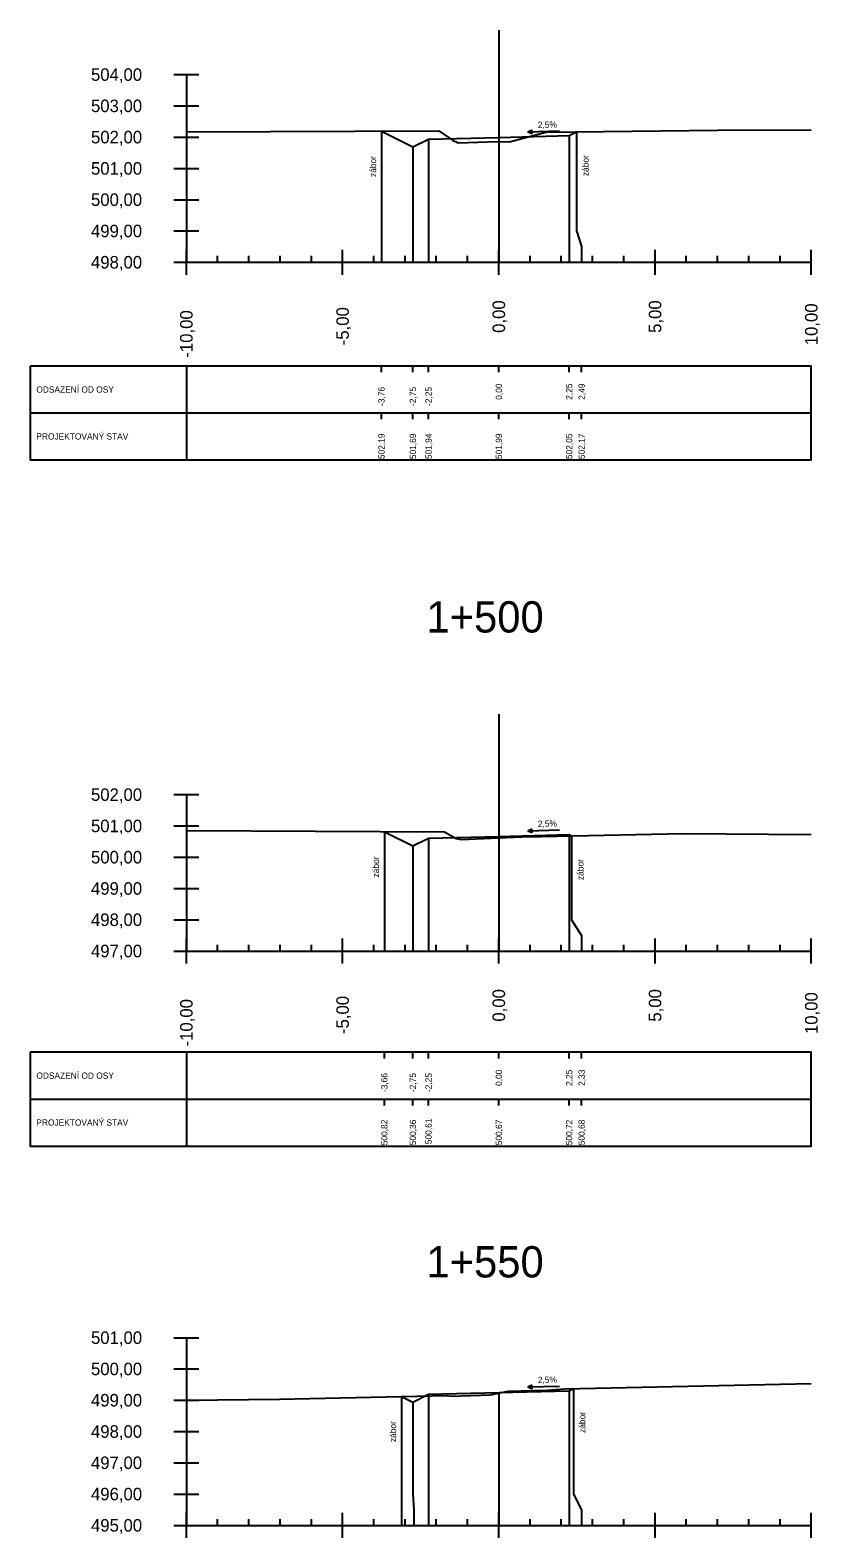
# Model space of a CAD drawing. Extents: x -631407 to -631215, y -1089700 to -1088598.
# Drawn here: x -631314.72 to -631289.44, y -1088856.74 to -1088808.54 of the extents above; entities that cross this region are included whole.
import ezdxf

# ---------------------------------------------------------------- set-up
doc = ezdxf.new("R2010")
doc.units = 0
for name, color, linetype in [('59', 7, 'Continuous'), ('NIVELETA_VYSKY', 7, 'Continuous'), ('REZ_BODY', 7, 'Continuous'), ('REZ_ODSTUPY', 7, 'Continuous'), ('REZ_POPIS', 7, 'Continuous'), ('REZ_RAMY', 7, 'Continuous'), ('REZ_STANICENI', 7, 'Continuous'), ('REZ_SVISLE', 7, 'Continuous'), ('REZ_TENKA', 7, 'Continuous'), ('REZ_TLUSTA', 7, 'Continuous'), ('TABULKA_POPIS', 7, 'Continuous'), ('TEREN', 7, 'Continuous'), ('zábor', 7, 'Continuous')]:
    doc.layers.add(name, color=color, linetype=linetype)

msp = doc.modelspace()

# ---------------------------------------------------------------- linework, layer by layer
at = {"layer": '59'}
for p, q in [((-631310.116, -1088809.959), (-631309.316, -1088809.959)), ((-631309.716, -1088809.959), (-631309.716, -1088815.959)), ((-631310.116, -1088810.959), (-631309.316, -1088810.959)), ((-631310.116, -1088811.959), (-631309.316, -1088811.959)), ((-631310.116, -1088812.959), (-631309.316, -1088812.959)), ((-631310.116, -1088813.959), (-631309.316, -1088813.959)), ((-631310.116, -1088814.959), (-631309.316, -1088814.959)), ((-631310.116, -1088815.959), (-631309.316, -1088815.959)), ((-631310.116, -1088832.981), (-631309.316, -1088832.981)), ((-631309.716, -1088832.981), (-631309.716, -1088837.981)), ((-631310.116, -1088833.981), (-631309.316, -1088833.981)), ((-631310.116, -1088834.981), (-631309.316, -1088834.981)), ((-631310.116, -1088835.981), (-631309.316, -1088835.981)), ((-631310.116, -1088836.981), (-631309.316, -1088836.981)), ((-631310.116, -1088837.981), (-631309.316, -1088837.981)), ((-631310.116, -1088850.343), (-631309.316, -1088850.343)), ((-631309.716, -1088850.343), (-631309.716, -1088856.343)), ((-631310.116, -1088851.343), (-631309.316, -1088851.343)), ((-631310.116, -1088852.343), (-631309.316, -1088852.343)), ((-631310.116, -1088853.343), (-631309.316, -1088853.343)), ((-631310.116, -1088854.343), (-631309.316, -1088854.343)), ((-631310.116, -1088855.343), (-631309.316, -1088855.343)), ((-631310.116, -1088856.343), (-631309.316, -1088856.343))]:
    msp.add_line(p, q, dxfattribs=at)
at = {"layer": 'REZ_RAMY'}
for p, q in [((-631314.716, -1088819.278), (-631314.716, -1088822.278)), ((-631309.716, -1088819.278), (-631309.716, -1088822.278)), ((-631303.472, -1088819.478), (-631303.472, -1088819.278)), ((-631302.466, -1088819.478), (-631302.466, -1088819.278)), ((-631301.966, -1088819.478), (-631301.966, -1088819.278)), ((-631299.716, -1088819.478), (-631299.716, -1088819.278)), ((-631297.466, -1088819.478), (-631297.466, -1088819.278)), ((-631297.066, -1088819.478), (-631297.066, -1088819.278)), ((-631314.716, -1088820.778), (-631289.716, -1088820.778)), ((-631303.472, -1088820.978), (-631303.472, -1088820.778)), ((-631302.466, -1088820.978), (-631302.466, -1088820.778)), ((-631301.966, -1088820.978), (-631301.966, -1088820.778)), ((-631299.716, -1088820.978), (-631299.716, -1088820.778)), ((-631297.466, -1088820.978), (-631297.466, -1088820.778)), ((-631297.066, -1088820.978), (-631297.066, -1088820.778)), ((-631314.716, -1088841.215), (-631314.716, -1088844.215)), ((-631309.716, -1088841.215), (-631309.716, -1088844.215)), ((-631303.38, -1088841.415), (-631303.38, -1088841.215)), ((-631302.466, -1088841.415), (-631302.466, -1088841.215)), ((-631301.966, -1088841.415), (-631301.966, -1088841.215)), ((-631299.716, -1088841.415), (-631299.716, -1088841.215)), ((-631297.466, -1088841.415), (-631297.466, -1088841.215)), ((-631297.066, -1088841.415), (-631297.066, -1088841.215)), ((-631314.716, -1088842.715), (-631289.716, -1088842.715)), ((-631303.38, -1088842.915), (-631303.38, -1088842.715)), ((-631302.466, -1088842.915), (-631302.466, -1088842.715)), ((-631301.966, -1088842.915), (-631301.966, -1088842.715)), ((-631299.716, -1088842.915), (-631299.716, -1088842.715)), ((-631297.466, -1088842.915), (-631297.466, -1088842.715)), ((-631297.066, -1088842.915), (-631297.066, -1088842.715))]:
    msp.add_line(p, q, dxfattribs=at)
for points in [[(-631314.716, -1088819.278), (-631314.716, -1088822.278), (-631289.716, -1088822.278), (-631289.716, -1088819.278)], [(-631314.716, -1088841.215), (-631314.716, -1088844.215), (-631289.716, -1088844.215), (-631289.716, -1088841.215)]]:
    msp.add_lwpolyline(points, close=True, dxfattribs=at)
at = {"layer": 'REZ_SVISLE'}
for points in [[(-631303.472, -1088811.77), (-631303.472, -1088814.959), (-631303.472, -1088815.459), (-631303.472, -1088815.959)], [(-631297.466, -1088811.911), (-631297.466, -1088814.959), (-631297.466, -1088815.459), (-631297.466, -1088815.959)], [(-631297.226, -1088811.791), (-631297.226, -1088814.959), (-631297.066, -1088815.459), (-631297.066, -1088815.959)], [(-631302.466, -1088812.274), (-631302.466, -1088814.959), (-631302.466, -1088815.459), (-631302.466, -1088815.959)], [(-631301.966, -1088812.024), (-631301.966, -1088814.959), (-631301.966, -1088815.459), (-631301.966, -1088815.959)], [(-631299.716, -1088811.967), (-631299.716, -1088814.959), (-631299.716, -1088815.459), (-631299.716, -1088815.959)], [(-631303.38, -1088834.165), (-631303.38, -1088836.981), (-631303.38, -1088837.481), (-631303.38, -1088837.981)], [(-631301.966, -1088834.372), (-631301.966, -1088836.981), (-631301.966, -1088837.481), (-631301.966, -1088837.981)], [(-631299.716, -1088834.316), (-631299.716, -1088836.981), (-631299.716, -1088837.481), (-631299.716, -1088837.981)], [(-631297.466, -1088834.259), (-631297.466, -1088836.981), (-631297.466, -1088837.481), (-631297.466, -1088837.981)], [(-631297.389, -1088834.298), (-631297.389, -1088836.981), (-631297.066, -1088837.481), (-631297.066, -1088837.981)], [(-631302.466, -1088834.622), (-631302.466, -1088836.981), (-631302.466, -1088837.481), (-631302.466, -1088837.981)], [(-631302.833, -1088852.22), (-631302.833, -1088855.343), (-631302.833, -1088855.843), (-631302.833, -1088856.343)], [(-631302.466, -1088852.403), (-631302.466, -1088855.343), (-631302.433, -1088855.843), (-631302.433, -1088856.343)], [(-631301.966, -1088852.153), (-631301.966, -1088855.343), (-631301.966, -1088855.843), (-631301.966, -1088856.343)], [(-631299.716, -1088852.097), (-631299.716, -1088855.343), (-631299.716, -1088855.843), (-631299.716, -1088856.343)], [(-631297.466, -1088852.041), (-631297.466, -1088855.343), (-631297.466, -1088855.843), (-631297.466, -1088856.343)], [(-631297.331, -1088851.973), (-631297.331, -1088855.343), (-631297.066, -1088855.843), (-631297.066, -1088856.343)]]:
    msp.add_lwpolyline(points, dxfattribs=at)
at = {"layer": 'REZ_TENKA'}
for p, q in [((-631308.716, -1088815.959), (-631308.716, -1088815.759)), ((-631307.716, -1088815.959), (-631307.716, -1088815.759)), ((-631306.716, -1088815.959), (-631306.716, -1088815.759)), ((-631305.716, -1088815.959), (-631305.716, -1088815.759)), ((-631303.716, -1088815.959), (-631303.716, -1088815.759)), ((-631302.716, -1088815.959), (-631302.716, -1088815.759)), ((-631301.716, -1088815.959), (-631301.716, -1088815.759)), ((-631300.716, -1088815.959), (-631300.716, -1088815.759)), ((-631298.716, -1088815.959), (-631298.716, -1088815.759)), ((-631297.716, -1088815.959), (-631297.716, -1088815.759)), ((-631296.716, -1088815.959), (-631296.716, -1088815.759)), ((-631295.716, -1088815.959), (-631295.716, -1088815.759)), ((-631293.716, -1088815.959), (-631293.716, -1088815.759)), ((-631292.716, -1088815.959), (-631292.716, -1088815.759)), ((-631291.716, -1088815.959), (-631291.716, -1088815.759)), ((-631290.716, -1088815.959), (-631290.716, -1088815.759)), ((-631308.716, -1088837.981), (-631308.716, -1088837.781)), ((-631307.716, -1088837.981), (-631307.716, -1088837.781)), ((-631306.716, -1088837.981), (-631306.716, -1088837.781)), ((-631305.716, -1088837.981), (-631305.716, -1088837.781)), ((-631303.716, -1088837.981), (-631303.716, -1088837.781)), ((-631302.716, -1088837.981), (-631302.716, -1088837.781)), ((-631301.716, -1088837.981), (-631301.716, -1088837.781)), ((-631300.716, -1088837.981), (-631300.716, -1088837.781)), ((-631298.716, -1088837.981), (-631298.716, -1088837.781)), ((-631297.716, -1088837.981), (-631297.716, -1088837.781)), ((-631296.716, -1088837.981), (-631296.716, -1088837.781)), ((-631295.716, -1088837.981), (-631295.716, -1088837.781)), ((-631293.716, -1088837.981), (-631293.716, -1088837.781)), ((-631292.716, -1088837.981), (-631292.716, -1088837.781)), ((-631291.716, -1088837.981), (-631291.716, -1088837.781)), ((-631290.716, -1088837.981), (-631290.716, -1088837.781)), ((-631308.716, -1088856.343), (-631308.716, -1088856.143)), ((-631307.716, -1088856.343), (-631307.716, -1088856.143)), ((-631306.716, -1088856.343), (-631306.716, -1088856.143)), ((-631305.716, -1088856.343), (-631305.716, -1088856.143)), ((-631303.716, -1088856.343), (-631303.716, -1088856.143)), ((-631302.716, -1088856.343), (-631302.716, -1088856.143)), ((-631301.716, -1088856.343), (-631301.716, -1088856.143)), ((-631300.716, -1088856.343), (-631300.716, -1088856.143)), ((-631298.716, -1088856.343), (-631298.716, -1088856.143)), ((-631297.716, -1088856.343), (-631297.716, -1088856.143)), ((-631296.716, -1088856.343), (-631296.716, -1088856.143)), ((-631295.716, -1088856.343), (-631295.716, -1088856.143)), ((-631293.716, -1088856.343), (-631293.716, -1088856.143)), ((-631292.716, -1088856.343), (-631292.716, -1088856.143)), ((-631291.716, -1088856.343), (-631291.716, -1088856.143)), ((-631290.716, -1088856.343), (-631290.716, -1088856.143))]:
    msp.add_line(p, q, dxfattribs=at)
at = {"layer": 'REZ_TLUSTA'}
for p, q in [((-631299.716, -1088808.539), (-631299.716, -1088815.959)), ((-631309.716, -1088816.359), (-631309.716, -1088815.559)), ((-631304.716, -1088816.359), (-631304.716, -1088815.559)), ((-631299.716, -1088816.359), (-631299.716, -1088815.559)), ((-631294.716, -1088816.359), (-631294.716, -1088815.559)), ((-631289.716, -1088816.359), (-631289.716, -1088815.559)), ((-631309.716, -1088815.959), (-631289.716, -1088815.959)), ((-631299.716, -1088830.408), (-631299.716, -1088837.981)), ((-631309.716, -1088838.381), (-631309.716, -1088837.581)), ((-631309.716, -1088837.981), (-631289.716, -1088837.981)), ((-631304.716, -1088838.381), (-631304.716, -1088837.581)), ((-631299.716, -1088838.381), (-631299.716, -1088837.581)), ((-631294.716, -1088838.381), (-631294.716, -1088837.581)), ((-631289.716, -1088838.381), (-631289.716, -1088837.581)), ((-631299.716, -1088852.343), (-631299.716, -1088856.343)), ((-631309.716, -1088856.743), (-631309.716, -1088855.943)), ((-631304.716, -1088856.743), (-631304.716, -1088855.943)), ((-631299.716, -1088856.743), (-631299.716, -1088855.943)), ((-631294.716, -1088856.743), (-631294.716, -1088855.943)), ((-631289.716, -1088856.743), (-631289.716, -1088855.943)), ((-631309.716, -1088856.343), (-631289.716, -1088856.343))]:
    msp.add_line(p, q, dxfattribs=at)
at = {"layer": 'TEREN'}
for points in [[(-631309.716, -1088811.795), (-631301.639, -1088811.763), (-631301.2, -1088812.053), (-631301.019, -1088812.14), (-631299.754, -1088812.104), (-631299.369, -1088812.105), (-631298.416, -1088811.851), (-631298.185, -1088811.803), (-631292.714, -1088811.737), (-631289.716, -1088811.722)], [(-631303.472, -1088811.77), (-631302.466, -1088812.274), (-631301.966, -1088812.024), (-631299.716, -1088811.967), (-631297.466, -1088811.911), (-631297.226, -1088811.791)], [(-631309.716, -1088834.131), (-631301.453, -1088834.175), (-631301.076, -1088834.384), (-631300.921, -1088834.414), (-631298.986, -1088834.333), (-631298.365, -1088834.317), (-631293.815, -1088834.228), (-631289.716, -1088834.258)], [(-631303.38, -1088834.165), (-631302.466, -1088834.622), (-631301.966, -1088834.372), (-631299.716, -1088834.316), (-631297.466, -1088834.259), (-631297.389, -1088834.298)], [(-631309.716, -1088852.344), (-631306.738, -1088852.308), (-631301.372, -1088852.187), (-631301.253, -1088852.209), (-631299.982, -1088852.17), (-631299.42, -1088852.053), (-631298.183, -1088852.024), (-631297.601, -1088851.98), (-631289.716, -1088851.804)], [(-631302.833, -1088852.22), (-631302.466, -1088852.403), (-631301.966, -1088852.153), (-631299.716, -1088852.097), (-631297.466, -1088852.041), (-631297.331, -1088851.973)]]:
    msp.add_lwpolyline(points, dxfattribs=at)
at = {"layer": 'zábor'}
for p, q in [((-631298.783, -1088811.788), (-631298.646, -1088811.723)), ((-631298.783, -1088811.788), (-631297.775, -1088811.763)), ((-631298.783, -1088811.788), (-631298.643, -1088811.846)), ((-631298.783, -1088834.136), (-631298.646, -1088834.071)), ((-631298.783, -1088834.136), (-631297.775, -1088834.111)), ((-631298.783, -1088834.136), (-631298.643, -1088834.194)), ((-631298.783, -1088851.918), (-631298.646, -1088851.853)), ((-631298.783, -1088851.918), (-631297.775, -1088851.892)), ((-631298.783, -1088851.918), (-631298.643, -1088851.975))]:
    msp.add_line(p, q, dxfattribs=at)

# ---------------------------------------------------------------- texts
at = {"layer": 'NIVELETA_VYSKY'}
for s, p in [('502,19', (-631303.372, -1088822.254)), ('501,69', (-631302.366, -1088822.254)), ('501,94', (-631301.866, -1088822.254)), ('501,99', (-631299.616, -1088822.254)), ('502,05', (-631297.366, -1088822.254)), ('502,17', (-631296.966, -1088822.254)), ('500,82', (-631303.28, -1088844.191)), ('500,36', (-631302.366, -1088844.191)), ('500,61', (-631301.866, -1088844.157)), ('500,67', (-631299.616, -1088844.191)), ('500,72', (-631297.366, -1088844.191)), ('500,68', (-631296.966, -1088844.191))]:
    msp.add_text(s, height=0.2, rotation=90, dxfattribs=at).set_placement(p)
at = {"layer": 'REZ_BODY'}
for s, p in [('-3,76', (-631303.372, -1088820.555)), ('-2,75', (-631302.366, -1088820.555)), ('-2,25', (-631301.866, -1088820.555)), ('0,00', (-631299.616, -1088820.357)), ('2,25', (-631297.366, -1088820.357)), ('2,49', (-631296.966, -1088820.357)), ('0,00', (-631299.616, -1088842.294)), ('2,25', (-631297.366, -1088842.294)), ('2,33', (-631296.966, -1088842.294)), ('-3,66', (-631303.28, -1088842.492)), ('-2,75', (-631302.366, -1088842.492)), ('-2,25', (-631301.866, -1088842.492))]:
    msp.add_text(s, height=0.2, rotation=90, dxfattribs=at).set_placement(p)
at = {"layer": 'REZ_ODSTUPY'}
for s, p in [('0,00', (-631299.516, -1088818.218)), ('5,00', (-631294.516, -1088818.218)), ('-10,00', (-631309.516, -1088819.011)), ('-5,00', (-631304.516, -1088818.614)), ('10,00', (-631289.516, -1088818.614)), ('0,00', (-631299.516, -1088840.239)), ('5,00', (-631294.516, -1088840.239)), ('10,00', (-631289.516, -1088840.636)), ('-10,00', (-631309.516, -1088841.033)), ('-5,00', (-631304.516, -1088840.636))]:
    msp.add_text(s, height=0.4, rotation=90, dxfattribs=at).set_placement(p)
at = {"layer": 'REZ_POPIS'}
for s, p in [('504,00', (-631312.768, -1088810.159)), ('503,00', (-631312.768, -1088811.159)), ('502,00', (-631312.768, -1088812.159)), ('501,00', (-631312.768, -1088813.159)), ('500,00', (-631312.768, -1088814.159)), ('499,00', (-631312.768, -1088815.159)), ('498,00', (-631312.768, -1088816.159)), ('502,00', (-631312.768, -1088833.181)), ('501,00', (-631312.768, -1088834.181)), ('500,00', (-631312.768, -1088835.181)), ('499,00', (-631312.768, -1088836.181)), ('498,00', (-631312.768, -1088837.181)), ('497,00', (-631312.768, -1088838.181)), ('501,00', (-631312.768, -1088850.543)), ('500,00', (-631312.768, -1088851.543)), ('499,00', (-631312.768, -1088852.543)), ('498,00', (-631312.768, -1088853.543)), ('497,00', (-631312.768, -1088854.543)), ('496,00', (-631312.768, -1088855.543)), ('495,00', (-631312.768, -1088856.543))]:
    msp.add_text(s, height=0.4, dxfattribs=at).set_placement(p)
at = {"layer": 'REZ_STANICENI'}
for s, p in [('1+500', (-631302.035, -1088827.798)), ('1+550', (-631302.035, -1088848.417))]:
    msp.add_text(s, height=1, dxfattribs=at).set_placement(p)
at = {"layer": 'TABULKA_POPIS'}
for s, p in [('ODSAZENÍ OD OSY', (-631314.516, -1088820.128)), ('PROJEKTOVANÝ STAV', (-631314.516, -1088821.628)), ('ODSAZENÍ OD OSY', (-631314.516, -1088842.065)), ('PROJEKTOVANÝ STAV', (-631314.516, -1088843.565))]:
    msp.add_text(s, height=0.2, dxfattribs=at).set_placement(p)
at = {"layer": 'zábor'}
for s, rotation, p in [('2,5%', 1.4321, (-631298.466, -1088811.667)), ('zábor', 90, (-631303.642, -1088813.234)), ('zábor', 90, (-631296.843, -1088813.206)), ('2,5%', 1.4321, (-631298.466, -1088834.015)), ('zábor', 90, (-631303.55, -1088835.628)), ('zábor', 90, (-631297.006, -1088835.712)), ('2,5%', 1.4321, (-631298.466, -1088851.797)), ('zábor', 90, (-631296.948, -1088853.388)), ('zábor', 90, (-631303.003, -1088853.683))]:
    msp.add_text(s, height=0.2, rotation=rotation, dxfattribs=at).set_placement(p)

doc.saveas('drawing.dxf')
